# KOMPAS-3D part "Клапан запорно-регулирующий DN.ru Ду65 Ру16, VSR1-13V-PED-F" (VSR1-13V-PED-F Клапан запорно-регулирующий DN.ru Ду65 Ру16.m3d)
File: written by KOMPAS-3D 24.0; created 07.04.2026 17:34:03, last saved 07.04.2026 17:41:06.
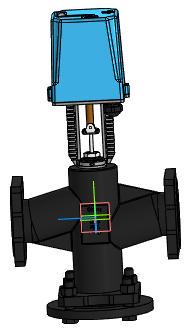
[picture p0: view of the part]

Document properties: Автор: R2D2; Полное имя файла: E:\Работа\Зайцев\Солянка\VSR1-13V-PED-F Клапан запорно-регулирующий DN.ru\DN65\VSR1-13V-PED-F Клапан запорно-регулирующий DN.ru Ду65 Ру16.m3d

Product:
- Part/product: Клапан запорно-регулирующий DN.ru Ду65 Ру16  | designation VSR1-13V-PED-F
    Масса: 17.2
    Раздел спецификации: Прочие изделия
    Примечание: D090-02892

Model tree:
1. Операция без истории:1  (labels: SHAPEOBJECT3D_ATTR_BUTT)

Expressions: VSR1-13V-PED-F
